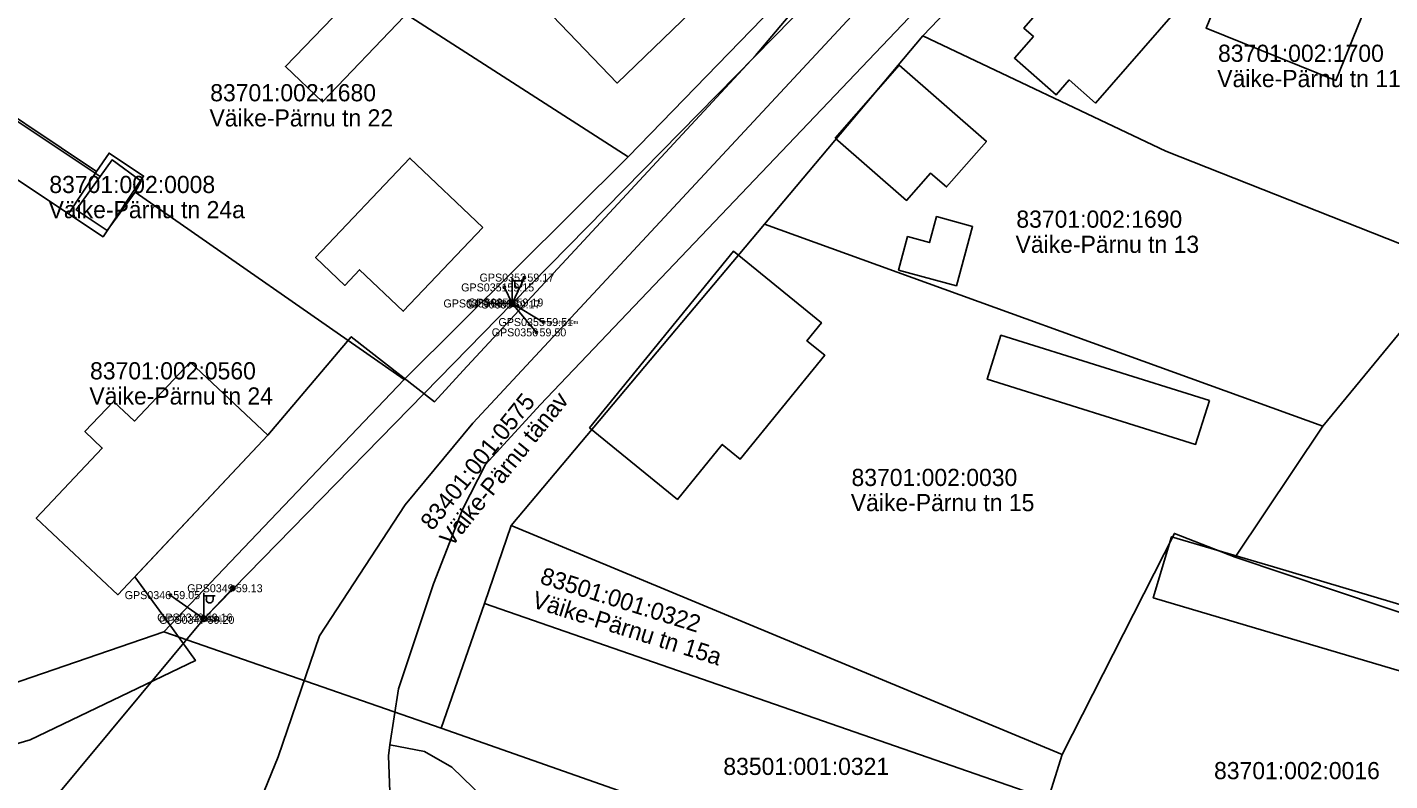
# Model space of a CAD drawing. Extents: x 580119 to 583377, y 6518915 to 6520820.
# Drawn here: x 581868.2 to 581987.4, y 6519761.7 to 6519827.6 of the extents above; entities that cross this region are included whole.
import ezdxf

# ---------------------------------------------------------------- set-up
doc = ezdxf.new("R2010")
doc.units = 0
for name, color, linetype in [('Hoone Elu- või ühiskondlik hoone', 7, 'Continuous'), ('Hoone Kõrval- või tootmishoone', 7, 'Continuous'), ('L_AADRESS', 7, 'Continuous'), ('MAAMUDEL', 7, 'Continuous'), ('MOOTKORG-EH2000', 7, 'Continuous'), ('MOOTMPUNKT', 7, 'Continuous'), ('MOOTNR', 7, 'Continuous'), ('MPOHULIIN', 7, 'Continuous'), ('PIIR', 7, 'Continuous'), ('POST', 7, 'Continuous'), ('SIOHULIIN', 7, 'Continuous'), ('Tee Liiklusala', 7, 'Continuous'), ('Tee Rada Püsikate', 7, 'Continuous'), ('Tee Tänav Püsikate', 7, 'Continuous'), ('TUNNUS', 7, 'Continuous')]:
    doc.layers.add(name, color=color, linetype=linetype)

msp = doc.modelspace()

# ---------------------------------------------------------------- linework, layer by layer
at = {"layer": 'Hoone Elu- või ühiskondlik hoone'}
for points in [[(581926.26, 6519828.92), (581919.8, 6519822.72), (581914.17, 6519828.6), (581920.63, 6519834.8)], [(581960.27, 6519835.05), (581961.44, 6519834.02), (581962.07, 6519834.73), (581968.65, 6519828.98), (581961.65, 6519820.98), (581959.35, 6519823), (581958.22, 6519821.71), (581954.56, 6519824.91), (581956.22, 6519826.79), (581955.37, 6519827.53), (581958.39, 6519830.98), (581957.44, 6519831.81)], [(581938.89, 6519817.92), (581944.47, 6519824.3), (581952.11, 6519817.63), (581948.62, 6519813.64), (581947.22, 6519814.86), (581945.13, 6519812.46)], [(581908.07, 6519810.09), (581901.1, 6519802.78), (581897.28, 6519806.4), (581895.99, 6519805.04), (581893.43, 6519807.47), (581901.69, 6519816.16)], [(581917.39, 6519792.59), (581929.99, 6519808.04), (581937.68, 6519801.77), (581936.41, 6519800.2), (581937.97, 6519798.93), (581930.58, 6519789.85), (581929, 6519791.13), (581925.08, 6519786.32)], [(581882.47, 6519798.34), (581889.27, 6519791.94), (581876.14, 6519778), (581869.01, 6519784.7), (581874.77, 6519790.82), (581873.26, 6519792.25), (581875.76, 6519794.9), (581877.61, 6519793.17)]]:
    msp.add_lwpolyline(points, close=True, dxfattribs=at)
at = {"layer": 'Hoone Kõrval- või tootmishoone'}
for points in [[(581985.65, 6519830.29), (581982.68, 6519822.95), (581971.33, 6519827.53), (581974.3, 6519834.87)], [(581901.18, 6519828.53), (581894.04, 6519821.07), (581890.8, 6519824.16), (581894.94, 6519828.47), (581893.66, 6519829.7), (581896.66, 6519832.85)], [(581874.28, 6519814.99), (581871.83, 6519811.3), (581859.33, 6519819.64), (581861.8, 6519823.33)], [(581871.83, 6519811.3), (581874.28, 6519814.99), (581875.37, 6519816.61), (581878.39, 6519814.6), (581874.85, 6519809.29)], [(581944.42, 6519806.38), (581945.22, 6519809.3), (581947.13, 6519808.78), (581947.75, 6519811.05), (581950.9, 6519810.19), (581949.49, 6519805)], [(581971.61, 6519794.97), (581970.41, 6519791.13), (581952.18, 6519796.83), (581953.38, 6519800.68)], [(581994.84, 6519775.2), (581993.27, 6519769.87), (581966.71, 6519777.73), (581968.3, 6519783.06), (581977.22, 6519780.42)]]:
    msp.add_lwpolyline(points, close=True, dxfattribs=at)
at = {"layer": 'MOOTMPUNKT'}
for centre in [(581911.7, 6519805.72), (581909.95, 6519804.86), (581908.54, 6519803.46), (581910.51, 6519803.37), (581910.75, 6519803.54), (581913.35, 6519801.83), (581912.76, 6519800.93), (581880.73, 6519777.96), (581886.2, 6519778.56), (581883.57, 6519776), (581883.73, 6519775.8)]:
    msp.add_circle(centre, 0.1, dxfattribs=at)
at = {"layer": 'MPOHULIIN'}
for p, q in [((581910.63, 6519803.45), (581909.95, 6519804.86)), ((581910.63, 6519803.45), (581913.35, 6519801.83)), ((581883.65, 6519775.9), (581880.73, 6519777.96))]:
    msp.add_line(p, q, dxfattribs=at)
msp.add_lwpolyline([(581859.1, 6519746.43), (581883.65, 6519775.9), (581910.63, 6519803.45), (581938.38, 6519831.71), (581969.55, 6519863.69), (582004.1, 6519898.63), (582043.97, 6519939.12), (582079.7, 6519981.43), (582116.09, 6520024.19), (582121.9, 6520051.43)], dxfattribs=at)
at = {"layer": 'PIIR'}
for points in [[(581888.65, 6519861.81), (581892.4, 6519861.4), (581938.38, 6519834.43), (581920.78, 6519816.29), (581900.94, 6519829.02), (581897.43, 6519832.37), (581895.07, 6519832.71), (581876.19, 6519844.87)], [(581878.19, 6519814.14), (581875.63, 6519816.01), (581874.6, 6519814.57), (581861.96, 6519822.96), (581860.51, 6519823.58), (581876.19, 6519844.87), (581895.07, 6519832.71), (581897.43, 6519832.37), (581900.94, 6519829.02), (581920.78, 6519816.29), (581901.19, 6519796.81), (581877.65, 6519813.18)], [(581960.86, 6519841.8), (582005.64, 6519823.27), (581993.12, 6519806.77), (581967.8, 6519816.78), (581946.55, 6519826.84)], [(581946.55, 6519826.84), (581967.8, 6519816.78), (581993.12, 6519806.77), (581981.54, 6519792.74), (581932.71, 6519810.39)], [(581860.51, 6519823.58), (581861.96, 6519822.96), (581874.6, 6519814.57), (581872.5, 6519811.64), (581875.21, 6519809.84), (581877.65, 6519813.18), (581901.19, 6519796.81), (581880.15, 6519774.76), (581864.77, 6519769.48), (581852.28, 6519812.4)], [(581875.63, 6519816.01), (581878.19, 6519814.14), (581877.65, 6519813.18), (581875.21, 6519809.84), (581872.5, 6519811.64), (581874.6, 6519814.57)], [(581932.71, 6519810.39), (581981.54, 6519792.74), (581973.87, 6519781.29), (581968.56, 6519783.35), (581958.73, 6519764.03), (581910.53, 6519784.06)], [(581993.12, 6519806.77), (582020.42, 6519795.75), (582009.8, 6519769.27), (582000.11, 6519772.48), (581973.87, 6519781.29), (581981.54, 6519792.74)], [(581908.21, 6519777.23), (581910.53, 6519784.06), (581958.73, 6519764.03), (581957.52, 6519760.13)], [(581968.56, 6519783.35), (581973.87, 6519781.29), (582000.11, 6519772.48), (581989.22, 6519739.81), (581954.75, 6519751.32), (581957.52, 6519760.13), (581958.73, 6519764.03)], [(581904.42, 6519766.33), (581908.21, 6519777.23), (581957.52, 6519760.13), (581954.75, 6519751.32), (581989.22, 6519739.81), (581993.48, 6519738.42), (582025, 6519727.92), (581987.97, 6519734.16), (581938.22, 6519748.74), (581939.76, 6519753.92)]]:
    msp.add_lwpolyline(points, close=True, dxfattribs=at)
for points in [[(581960.86, 6519841.8), (581946.55, 6519826.84), (581932.71, 6519810.39), (581910.53, 6519784.06), (581908.21, 6519777.23), (581904.42, 6519766.33), (581880.15, 6519774.76), (581901.19, 6519796.81), (581920.78, 6519816.29), (581938.38, 6519834.43)], [(581720.83, 6519828.38), (581751.53, 6519809.56), (581782.73, 6519790.33), (581814.17, 6519771.63), (581824.87, 6519768.18), (581842.25, 6519764.8), (581856.32, 6519767.48), (581864.77, 6519769.48), (581880.15, 6519774.76), (581904.42, 6519766.33), (581939.76, 6519753.92), (581938.22, 6519748.74), (581987.97, 6519734.16), (582025, 6519727.92), (582043.82, 6519724.92), (582041.99, 6519717.52), (582191.36, 6519685.62), (582375.21, 6519645.73)]]:
    msp.add_lwpolyline(points, dxfattribs=at)
at = {"layer": 'POST'}
for p, q in [((581910.63, 6519803.7), (581910.63, 6519805.7)), ((581910.63, 6519805.45), (581911.63, 6519805.45)), ((581910.85, 6519805.13), (581910.85, 6519805.45)), ((581911.47, 6519805.13), (581911.47, 6519805.45)), ((581910.63, 6519803.45), (581910.63, 6519803.45)), ((581883.65, 6519776.15), (581883.65, 6519778.15)), ((581883.65, 6519777.9), (581884.65, 6519777.9)), ((581883.88, 6519777.58), (581883.88, 6519777.9)), ((581884.49, 6519777.58), (581884.49, 6519777.9)), ((581883.65, 6519775.9), (581883.65, 6519775.9))]:
    msp.add_line(p, q, dxfattribs=at)
msp.add_lwpolyline([(581886.2, 6519778.56), (581883.65, 6519775.9)], dxfattribs=at)
for centre, radius in [((581910.63, 6519803.45), 0.25), ((581886.2, 6519778.56), 0.2), ((581883.65, 6519775.9), 0.25)]:
    msp.add_circle(centre, radius, dxfattribs=at)
for centre in [(581911.16, 6519805.13), (581884.18, 6519777.58)]:
    msp.add_arc(centre, 0.306, 180, 0, dxfattribs=at)
at = {"layer": 'SIOHULIIN'}
msp.add_line((581910.63, 6519803.45), (581911.7, 6519805.72), dxfattribs=at)
msp.add_lwpolyline([(581908.54, 6519803.46), (581910.63, 6519803.45), (581912.76, 6519800.93)], dxfattribs=at)
at = {"layer": 'Tee Liiklusala'}
for points in [[(581720.38, 6519828.52), (581720.95, 6519826.95), (581768.72, 6519797.3), (581810.21, 6519772.25), (581818.53, 6519768.42), (581826.6, 6519765.66), (581834.64, 6519763.76), (581840.22, 6519763.09), (581848.3, 6519762.14), (581861.54, 6519763.3), (581864.96, 6519764.3), (581868.47, 6519765.32), (581882.93, 6519772.24), (581880.53, 6519775.58), (581877.63, 6519779.57), (581889.27, 6519791.94), (581896.55, 6519800.55), (581903.84, 6519794.86), (581906.33, 6519797.61), (581931.92, 6519825.13), (581939.52, 6519834.18)], [(581945.92, 6519829.05), (581913.09, 6519794.59), (581908.31, 6519789.37), (581906.29, 6519785.46), (581903.76, 6519778.95), (581900.68, 6519769.78), (581899.94, 6519764.88), (581899.8, 6519763.92), (581900.03, 6519758.4), (581902.2, 6519754.19), (581905.73, 6519751.23), (581910.81, 6519749.68), (581921.31, 6519748.51), (581921.98, 6519748.3), (581922.49, 6519751.32), (581922.62, 6519752.14), (581960.46, 6519740.75), (581979.43, 6519735.65), (581990.12, 6519733.44), (581991.04, 6519736.96), (582026.29, 6519725.99), (582044.12, 6519722.1)]]:
    msp.add_lwpolyline(points, dxfattribs=at)
at = {"layer": 'Tee Rada Püsikate'}
msp.add_lwpolyline([(581899.94, 6519764.88), (581902.96, 6519764.3), (581905.34, 6519762.93), (581912.78, 6519755.72), (581916.04, 6519753.69), (581921.59, 6519751.61), (581922.49, 6519751.32), (581940.67, 6519745.53), (581963.85, 6519738.78), (581987.52, 6519732.79), (581989.83, 6519732.3)], dxfattribs=at)
at = {"layer": 'Tee Tänav Püsikate'}
for points in [[(581893.77, 6519774.39), (581901.27, 6519785.85), (581907.2, 6519792.99), (581946.17, 6519834.9)], [(581893.77, 6519774.39), (581890.16, 6519763.82), (581885.37, 6519752.11)]]:
    msp.add_lwpolyline(points, dxfattribs=at)

# ---------------------------------------------------------------- texts
at = {"layer": 'L_AADRESS'}
for s, p in [('Väike-Pärnu tn 11', (581972.3, 6519822.37)), ('Väike-Pärnu tn 22', (581884.16, 6519818.93)), ('Väike-Pärnu tn 24a', (581870.08, 6519810.91)), ('Väike-Pärnu tn 13', (581954.66, 6519807.88)), ('Väike-Pärnu tn 24', (581873.65, 6519794.62)), ('Väike-Pärnu tn 15', (581940.25, 6519785.3))]:
    msp.add_text(s, height=1.5, dxfattribs=at).set_placement(p)
for s, rotation, p in [('Väike-Pärnu tänav', 51.294, (581905.34, 6519782.09)), ('Väike-Pärnu tn 15a', 342.6259, (581912.27, 6519776.92))]:
    msp.add_text(s, height=1.5, rotation=rotation, dxfattribs=at).set_placement(p)
at = {"layer": 'MAAMUDEL'}
for s, p in [(' mp_ohl6.30m', (581913.35, 6519801.65)), (' kaabel', (581883.57, 6519775.83)), (' kaabel', (581883.73, 6519775.62))]:
    msp.add_text(s, height=0.35, dxfattribs=at).set_placement(p)
at = {"layer": 'MOOTKORG-EH2000'}
for s, p in [(' 59.17', (581911.7, 6519805.37)), (' 59.15', (581909.95, 6519804.51)), (' 59.10', (581908.54, 6519803.11)), (' 59.17', (581910.51, 6519803.02)), (' 59.19', (581910.75, 6519803.19)), (' 59.51', (581913.35, 6519801.48)), (' 59.50', (581912.76, 6519800.58)), (' 59.05', (581880.73, 6519777.61)), (' 59.13', (581886.2, 6519778.21)), (' 59.16', (581883.57, 6519775.65)), (' 59.20', (581883.73, 6519775.45))]:
    msp.add_text(s, height=0.7, dxfattribs=at).set_placement(p)
at = {"layer": 'MOOTNR'}
for s, p in [('GPS0352 ', (581907.78, 6519805.37)), ('GPS0351 ', (581906.17, 6519804.51)), ('GPS0350 ', (581904.62, 6519803.11)), ('GPS0353 ', (581906.59, 6519803.02)), ('GPS0354 ', (581906.76, 6519803.19)), ('GPS0355 ', (581909.43, 6519801.48)), ('GPS0356 ', (581908.84, 6519800.58)), ('GPS0346 ', (581876.74, 6519777.61)), ('GPS0349 ', (581882.21, 6519778.21)), ('GPS0348 ', (581879.58, 6519775.65)), ('GPS0347 ', (581879.74, 6519775.45))]:
    msp.add_text(s, height=0.7, dxfattribs=at).set_placement(p)
at = {"layer": 'TUNNUS'}
for s, p in [('83701:002:1700', (581972.37, 6519824.58)), ('83701:002:1680', (581884.22, 6519821.13)), ('83701:002:0008', (581870.15, 6519813.11)), ('83701:002:1690', (581954.73, 6519810.08)), ('83701:002:0560', (581873.71, 6519796.82)), ('83701:002:0030', (581940.31, 6519787.5)), ('83501:001:0321', (581929.1, 6519762.24)), ('83701:002:0016', (581972.02, 6519761.87))]:
    msp.add_text(s, height=1.5, dxfattribs=at).set_placement(p)
for s, rotation, p in [('83401:001:0575', 51.294, (581903.65, 6519783.52)), ('83501:001:0322', 342.6259, (581912.98, 6519779))]:
    msp.add_text(s, height=1.5, rotation=rotation, dxfattribs=at).set_placement(p)

doc.saveas('drawing.dxf')
